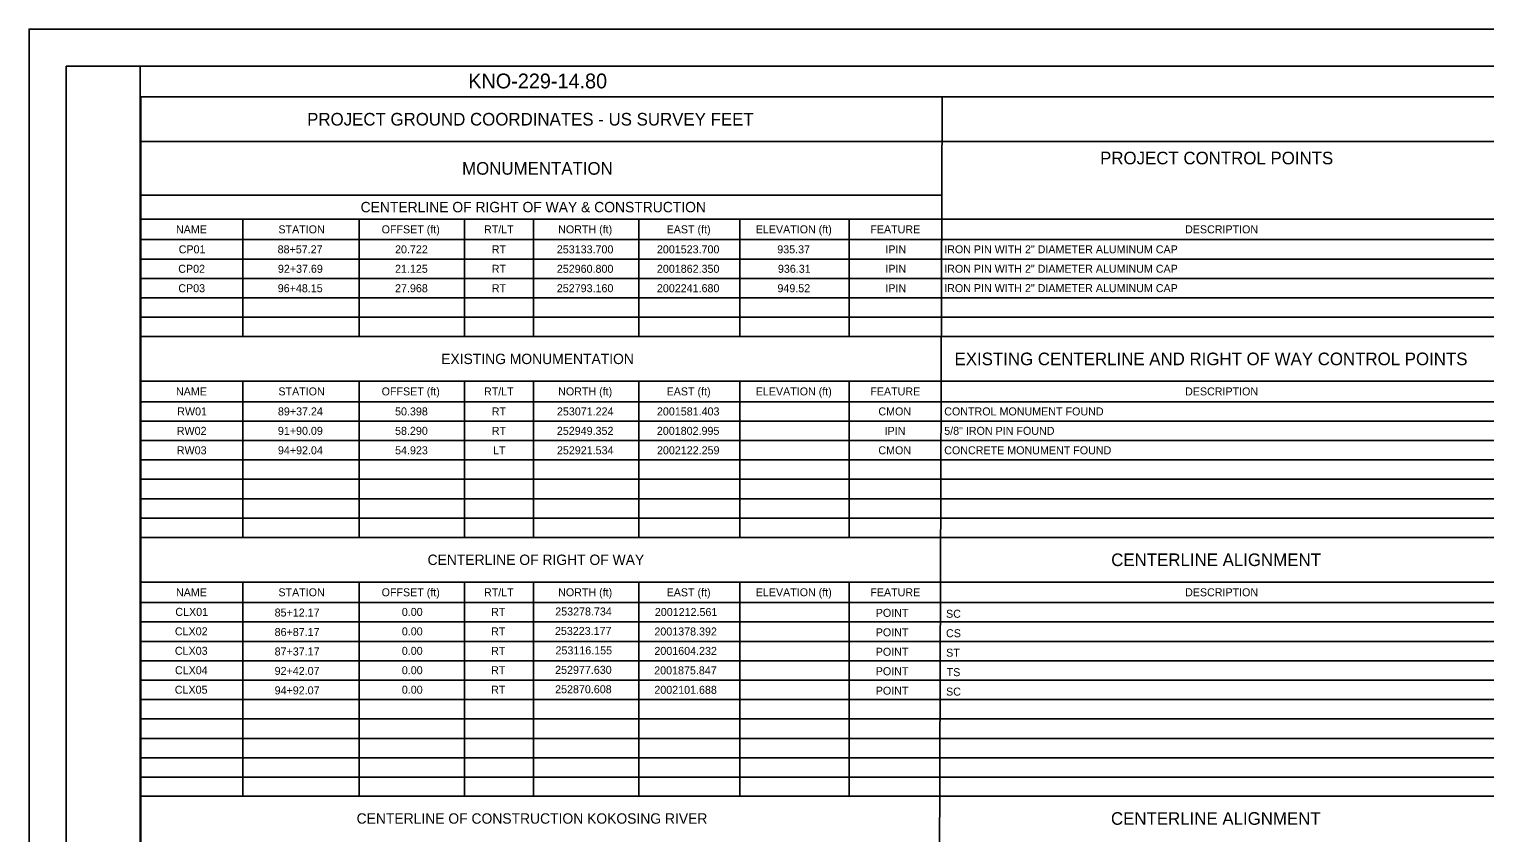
# Model space of a CAD drawing. Extents: x -4451 to 6119, y -1533 to 848.
# Drawn here: x 0 to 392.9, y 223.1 to 440 of the extents above; entities that cross this region are included whole.
import ezdxf

# ---------------------------------------------------------------- set-up
doc = ezdxf.new("R2010")
doc.units = 0
for name, color, linetype in [('SC_Scratch1', 7, 'Continuous'), ('SH_Cut_Line', 7, 'Continuous'), ('SH_Data', 7, 'Continuous')]:
    doc.layers.add(name, color=color, linetype=linetype)

msp = doc.modelspace()

# ---------------------------------------------------------------- linework, layer by layer
at = {"layer": 'SC_Scratch1'}
for p, q in [((30.12, 421.7), (640.12, 421.7)), ((30.12, 84.77), (30.12, 421.7)), ((245.17, 54.71), (246.43, 421.7)), ((30.12, 409.69), (246.43, 409.69)), ((246.43, 409.69), (397.85, 409.69)), ((30.12, 395.21), (246.43, 395.21)), ((30.12, 388.75), (579.55, 388.75)), ((57.7, 357.03), (57.7, 388.75)), ((89.07, 357.03), (89.07, 388.75)), ((117.46, 357.03), (117.46, 388.75)), ((136.11, 357.03), (136.11, 388.75)), ((164.51, 357.03), (164.51, 388.75)), ((191.81, 357.03), (191.81, 388.75)), ((221.29, 357.03), (221.29, 388.75)), ((30.12, 383.2), (246.43, 383.2)), ((246.43, 383.2), (640.12, 383.2)), ((30.12, 377.97), (640.12, 377.97)), ((30.12, 372.73), (640.12, 372.73)), ((30.12, 367.5), (640.12, 367.5)), ((30.12, 362.26), (640.12, 362.26)), ((30.12, 357.03), (640.12, 357.03)), ((30.12, 345.02), (579.55, 345.02)), ((57.7, 302.83), (57.7, 345.02)), ((89.07, 302.79), (89.07, 345.02)), ((117.46, 302.83), (117.46, 345.02)), ((136.11, 302.82), (136.11, 345.02)), ((164.51, 302.85), (164.51, 345.02)), ((191.81, 302.83), (191.81, 345.02)), ((221.29, 302.85), (221.29, 345.02)), ((30.12, 339.47), (640.12, 339.47)), ((30.12, 334.24), (640.12, 334.24)), ((30.12, 329), (640.12, 329)), ((30.12, 323.77), (640.12, 323.77)), ((30.12, 318.53), (640.12, 318.53)), ((30.12, 313.3), (640.12, 313.3)), ((30.12, 308.06), (640.12, 308.06)), ((30.12, 302.83), (640.12, 302.83)), ((30.12, 302.83), (640.12, 302.83)), ((30.12, 290.82), (579.55, 290.82)), ((57.7, 232.93), (57.7, 290.82)), ((89.07, 232.93), (89.07, 290.82)), ((117.46, 232.99), (117.46, 290.82)), ((136.11, 232.96), (136.11, 290.82)), ((164.51, 232.96), (164.51, 290.82)), ((191.81, 232.96), (191.81, 290.82)), ((221.29, 232.96), (221.29, 290.82)), ((30.12, 285.27), (640.12, 285.27)), ((30.12, 280.04), (640.12, 280.04)), ((30.12, 274.8), (640.12, 274.8)), ((30.12, 269.57), (640.12, 269.57)), ((30.12, 264.33), (640.12, 264.33)), ((30.12, 259.1), (640.12, 259.1)), ((30.12, 253.86), (640.12, 253.86)), ((30.12, 248.63), (640.12, 248.63)), ((30.12, 243.39), (640.12, 243.39)), ((30.12, 238.16), (640.12, 238.16)), ((30.05, 233.02), (640.05, 233.02)), ((30.05, 233.02), (640.05, 233.02)), ((30.05, 233.02), (640.05, 233.02))]:
    msp.add_line(p, q, dxfattribs=at)
at = {"layer": 'SH_Cut_Line'}
msp.add_lwpolyline([(0, 0), (680, 0), (680, 440), (0, 440)], close=True, dxfattribs=at)
at = {"layer": 'SH_Data'}
for points in [[(10, 430), (30, 430), (30, 10), (10, 10)], [(30, 430), (670, 430), (670, 10), (30, 10)]]:
    msp.add_lwpolyline(points, close=True, dxfattribs=at)

# ---------------------------------------------------------------- texts
at = {"layer": 'SC_Scratch1'}
for s, height, p in [('KNO-229-14.80', 4, (118.52, 424.01)), ('PROJECT GROUND COORDINATES - US SURVEY FEET', 3.4, (75.04, 413.99)), ('PROJECT CONTROL POINTS', 3.4, (289.04, 403.52)), ('MONUMENTATION ', 3.4, (116.85, 400.72)), ('CENTERLINE OF RIGHT OF WAY & CONSTRUCTION', 2.8, (89.47, 390.58)), ('NAME', 2.157, (39.64, 384.9)), ('STATION', 2.157, (67.28, 384.9)), ('OFFSET (ft)', 2.1565, (95.14, 384.9)), ('RT/LT', 2.157, (122.77, 384.9)), ('NORTH (ft)', 2.157, (142.78, 384.9)), ('EAST (ft)', 2.157, (172.05, 384.9)), ('ELEVATION (ft)', 2.1565, (196.11, 384.9)), ('FEATURE', 2.157, (227.02, 384.9)), ('DESCRIPTION', 2.1565, (311.97, 384.9)), ('CP01', 2.16, (40.37, 379.5)), ('88+57.27', 2.16, (67.07, 379.5)), ('20.722', 2.16, (98.76, 379.5)), ('RT', 2.16, (124.87, 379.5)), ('253133.700', 2.16, (142.42, 379.5)), ('2001523.700', 2.16, (169.43, 379.5)), ('935.37', 2.16, (201.91, 379.5)), ('IPIN', 2.16, (231.08, 379.5)), ('IRON PIN WITH 2" DIAMETER ALUMINUM CAP', 2.1565, (246.97, 379.51)), ('CP02', 2.16, (40.25, 374.25)), ('92+37.69', 2.16, (67.14, 374.25)), ('21.125', 2.16, (98.75, 374.25)), ('RT', 2.16, (124.87, 374.25)), ('252960.800', 2.16, (142.42, 374.25)), ('2001862.350', 2.16, (169.43, 374.25)), ('936.31', 2.16, (202.09, 374.25)), ('IPIN', 2.16, (231.08, 374.25)), ('IRON PIN WITH 2" DIAMETER ALUMINUM CAP', 2.1565, (246.97, 374.27)), ('CP03', 2.16, (40.26, 369.01)), ('96+48.15', 2.16, (67.1, 369.01)), ('27.968', 2.16, (98.76, 369.01)), ('RT', 2.16, (124.87, 369.01)), ('252793.160', 2.16, (142.42, 369.01)), ('2002241.680', 2.16, (169.43, 369.01)), ('949.52', 2.16, (201.96, 369.01)), ('IPIN', 2.16, (231.08, 369.01)), ('IRON PIN WITH 2" DIAMETER ALUMINUM CAP', 2.1565, (246.97, 369.04)), ('EXISTING MONUMENTATION', 2.8, (111.21, 349.62)), ('EXISTING CENTERLINE AND RIGHT OF WAY CONTROL POINTS', 3.4, (249.75, 349.32)), ('NAME', 2.157, (39.64, 341.17)), ('STATION', 2.157, (67.28, 341.17)), ('OFFSET (ft)', 2.1565, (95.14, 341.17)), ('RT/LT', 2.157, (122.77, 341.17)), ('NORTH (ft)', 2.157, (142.78, 341.17)), ('EAST (ft)', 2.157, (172.05, 341.17)), ('ELEVATION (ft)', 2.1565, (196.11, 341.17)), ('FEATURE', 2.157, (227.02, 341.17)), ('DESCRIPTION', 2.1565, (311.97, 341.17)), ('RW01', 2.16, (39.98, 335.77)), ('89+37.24', 2.16, (67.15, 335.77)), ('50.398', 2.16, (98.76, 335.77)), ('RT', 2.16, (124.87, 335.77)), ('253071.224', 2.16, (142.45, 335.77)), ('2001581.403', 2.16, (169.44, 335.77)), ('CMON', 2.16, (229.2, 335.77)), ('CONTROL MONUMENT FOUND', 2.16, (246.97, 335.77)), ('RW02', 2.16, (39.86, 330.53)), ('91+90.09', 2.16, (67.14, 330.53)), ('58.290', 2.16, (98.76, 330.53)), ('RT', 2.16, (124.87, 330.53)), ('252949.352', 2.16, (142.43, 330.53)), ('2001802.995', 2.16, (169.42, 330.53)), ('IPIN', 2.16, (230.88, 330.53)), ('5/8" IRON PIN FOUND ', 2.16, (246.97, 330.53)), ('RW03', 2.16, (39.87, 325.28)), ('94+92.04', 2.16, (67.15, 325.28)), ('54.923', 2.16, (98.77, 325.28)), ('LT', 2.16, (125.2, 325.28)), ('252921.534', 2.16, (142.45, 325.28)), ('2002122.259', 2.16, (169.45, 325.28)), ('CMON', 2.16, (229.2, 325.28)), ('CONCRETE MONUMENT FOUND', 2.16, (246.97, 325.28)), ('CENTERLINE OF RIGHT OF WAY ', 2.8, (107.54, 295.42)), ('CENTERLINE ALIGNMENT', 3.4, (292.04, 295.12)), ('NAME', 2.157, (39.64, 286.97)), ('STATION', 2.157, (67.28, 286.97)), ('OFFSET (ft)', 2.1565, (95.14, 286.97)), ('RT/LT', 2.157, (122.77, 286.97)), ('NORTH (ft)', 2.157, (142.78, 286.97)), ('EAST (ft)', 2.157, (172.05, 286.97)), ('ELEVATION (ft)', 2.1565, (196.11, 286.97)), ('FEATURE', 2.157, (227.02, 286.97)), ('DESCRIPTION', 2.1565, (311.97, 286.97)), ('CLX01', 2.16, (39.46, 281.68)), ('85+12.17', 2.16, (66.26, 281.5)), ('0.00', 2.16, (100.59, 281.67)), ('RT', 2.16, (124.69, 281.67)), ('253278.734', 2.16, (141.99, 281.79)), ('2001212.561', 2.16, (168.87, 281.64)), ('POINT', 2.16, (228.49, 281.42)), ('SC', 2.16, (247.46, 281.17)), ('CLX02', 2.16, (39.34, 276.43)), ('86+87.17', 2.16, (66.26, 276.25)), ('0.00', 2.16, (100.59, 276.42)), ('RT', 2.16, (124.69, 276.42)), ('253223.177', 2.16, (141.91, 276.54)), ('2001378.392', 2.16, (168.75, 276.39)), ('POINT', 2.16, (228.49, 276.17)), ('CS', 2.16, (247.46, 275.92)), ('CLX03', 2.16, (39.34, 271.18)), ('87+37.17', 2.16, (66.26, 271)), ('0.00', 2.16, (100.59, 271.17)), ('RT', 2.16, (124.69, 271.17)), ('253116.155', 2.16, (142.06, 271.29)), ('2001604.232', 2.16, (168.75, 271.15)), ('POINT', 2.16, (228.49, 270.92)), ('ST', 2.16, (247.49, 270.67)), ('CLX04', 2.16, (39.36, 265.93)), ('92+42.07', 2.16, (66.26, 265.75)), ('0.00', 2.16, (100.59, 265.93)), ('RT', 2.16, (124.69, 265.93)), ('252977.630', 2.16, (141.96, 266.04)), ('2001875.847', 2.16, (168.7, 265.9)), ('POINT', 2.16, (228.49, 265.67)), ('TS', 2.16, (247.63, 265.42)), ('CLX05', 2.16, (39.32, 260.68)), ('94+92.07', 2.16, (66.26, 260.5)), ('0.00', 2.16, (100.59, 260.68)), ('RT', 2.16, (124.69, 260.68)), ('252870.608', 2.16, (141.96, 260.8)), ('2002101.688', 2.16, (168.74, 260.65)), ('POINT', 2.16, (228.49, 260.42)), ('SC', 2.16, (247.46, 260.17)), ('CENTERLINE OF CONSTRUCTION KOKOSING RIVER', 2.8, (88.39, 225.61)), ('CENTERLINE ALIGNMENT', 3.4, (291.97, 225.31))]:
    msp.add_text(s, height=height, dxfattribs=at).set_placement(p)

doc.saveas('drawing.dxf')
